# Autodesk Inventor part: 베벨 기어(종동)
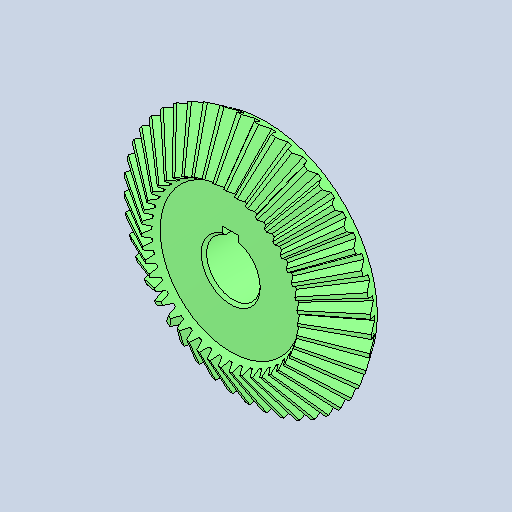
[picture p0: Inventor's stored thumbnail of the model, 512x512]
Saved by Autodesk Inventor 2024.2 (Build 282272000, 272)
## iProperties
Created: 2026-01
Part Number: 베벨 기어(종동)
Material: 강철, 합금
Document SubType Name: Modeling
Designer: home
Density: 7.73 g/cm^3
Appearance: 기본값
Author: jhkim
Sending System: Autodesk Inventor 2026
Preprocessor: ST-DEVELOPER v20.1
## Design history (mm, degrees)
feature "Solid1"
node "솔리드1"
